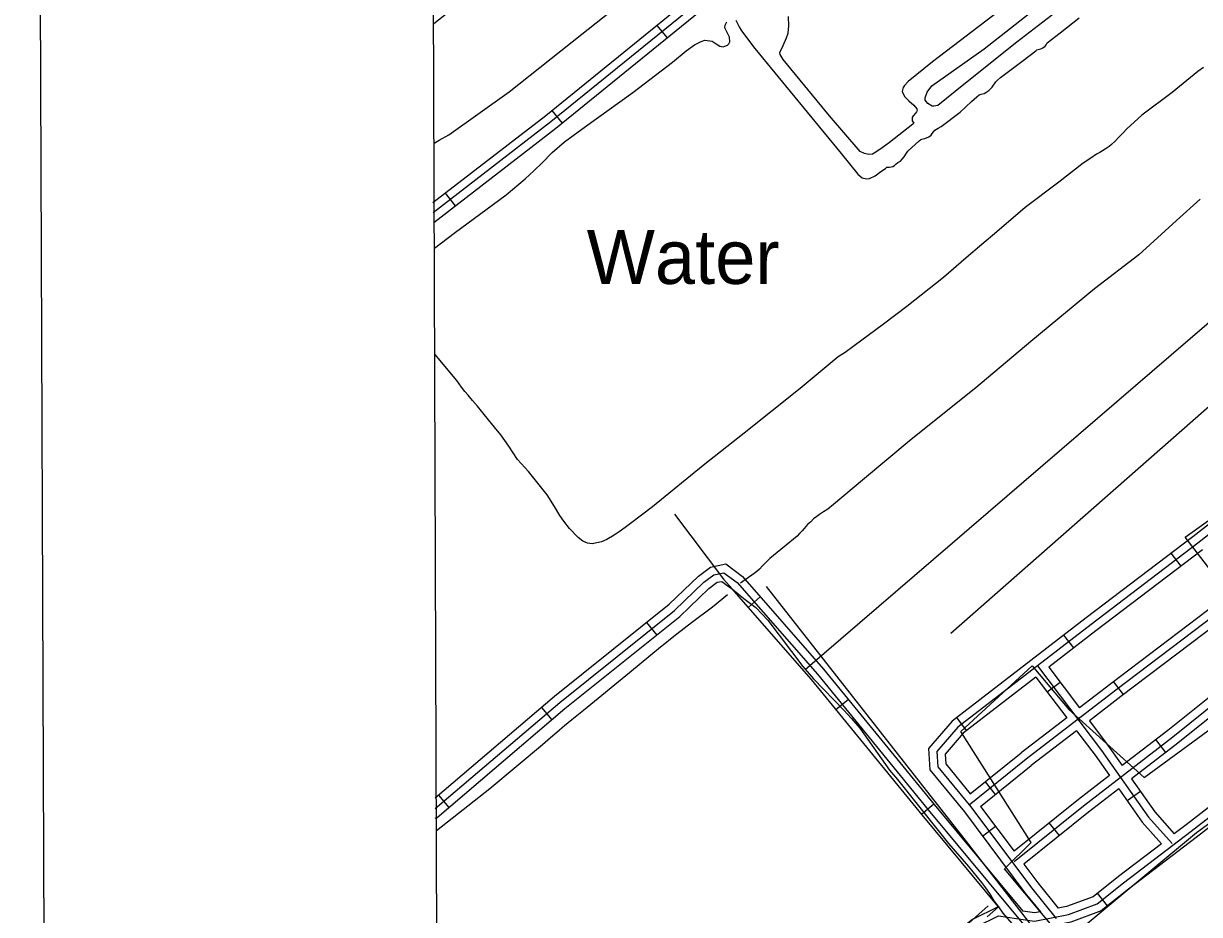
# Model space of a CAD drawing. Extents: x 3405885 to 3443815, y 558517 to 583997.
# Drawn here: x 3409221 to 3411396, y 573242 to 574891 of the extents above; entities that cross this region are included whole.
import ezdxf

# ---------------------------------------------------------------- set-up
doc = ezdxf.new("R2010")
doc.units = 0
for name, color, linetype in [('V-ANNO-SYMB', 7, 'Continuous'), ('V-DTCH-CNTR', 7, 'Continuous'), ('V-GRID-FRAM', 7, 'Continuous'), ('V-RIVR-IDEN', 7, 'Continuous'), ('V-ROAD-CNTR', 7, 'Continuous'), ('V-SITE-OTLN', 7, 'Continuous'), ('V-TOPO-SHOR', 7, 'Continuous')]:
    doc.layers.add(name, color=color, linetype=linetype)

msp = doc.modelspace()

# ---------------------------------------------------------------- linework, layer by layer
at = {"layer": 'V-ANNO-SYMB'}
msp.add_lwpolyline([(3409312.5, 559736.2), (3442395.5, 559868.5), (3442303.8, 582784.9), (3409220.9, 582652.6), (3409312.5, 559736.2)], dxfattribs=at)
at = {"layer": 'V-DTCH-CNTR'}
for points in [[(3410425.3, 573983.1), (3410515.7, 573863.2), (3410532.6, 573844.5), (3410553.2, 573826.9), (3410575.4, 573810.6), (3410587.5, 573798.3), (3410598, 573787.3), (3410662.3, 573701.5), (3410682.2, 573678.5), (3410738.4, 573620.8), (3410752.5, 573604.8), (3410768.1, 573587.5), (3410823, 573509.4), (3410837.5, 573492.5), (3410912.6, 573398), (3410931.8, 573373.5), (3410968.9, 573331), (3410977.1, 573321.4), (3410985, 573311.6), (3410992.8, 573301.6), (3411000.3, 573291.5), (3411007.7, 573281.3), (3411016, 573267.8), (3411024.2, 573256.4), (3411032.4, 573244.8), (3411111.8, 573153.4)], [(3411003.8, 573238), (3411024.2, 573256.4)]]:
    msp.add_lwpolyline(points, dxfattribs=at)
at = {"layer": 'V-GRID-FRAM'}
msp.add_lwpolyline([(3409954, 582088.9), (3441575.2, 582215.4), (3441655.9, 564032.2), (3410018.8, 563905.7), (3409954, 582088.9)], dxfattribs=at)
at = {"layer": 'V-ROAD-CNTR'}
for p, q in [((3410392.6, 574887.7), (3410411.5, 574864.4)), ((3410198.4, 574730.2), (3410217.3, 574706.9)), ((3410001, 574577.4), (3410019.4, 574553.6)), ((3411362.4, 573887.2), (3411344.2, 573911)), ((3410583.7, 573830.3), (3410561.2, 573810.5)), ((3410373.6, 573782.9), (3410392.3, 573759.5)), ((3411163.7, 573735.6), (3411145.4, 573759.4)), ((3411138.7, 573672), (3411114.7, 573653.9)), ((3411255.6, 573649.3), (3411237.5, 573673.3)), ((3410178.8, 573625.6), (3410198.2, 573602.7)), ((3410746.9, 573640.2), (3410723.6, 573621.2)), ((3410965.6, 573583), (3410947.3, 573606.8)), ((3411334, 573542.2), (3411315.7, 573566)), ((3410999.8, 573487.9), (3411018.6, 573464.5)), ((3409988.4, 573463.5), (3410007.9, 573440.6)), ((3411287.1, 573470.2), (3411262.6, 573453)), ((3410905.1, 573446.6), (3410881.8, 573427.7)), ((3411137.2, 573388.5), (3411118.5, 573411.9)), ((3411019.2, 573405), (3410995.1, 573387)), ((3411226.1, 573258.2), (3411207.5, 573281.8))]:
    msp.add_line(p, q, dxfattribs=at)
for points in [[(3409978.3, 574559.8), (3410186.8, 574720.9), (3410442.9, 574928.5)], [(3410468.6, 574930.1), (3410196.2, 574709.1), (3409978.4, 574540.9)], [(3409979.8, 574523.1), (3410205.5, 574697.3), (3410471, 574912.7)], [(3412013, 574429.4), (3412000.8, 574413), (3411589.4, 574101.5), (3411383.8, 573941.2)], [(3412025.1, 574420.5), (3412011.6, 574402.3), (3411598.5, 574089.6), (3411393.1, 573929.4)], [(3411384, 573941.3), (3411186.6, 573791.1), (3410938.6, 573600.1), (3410895.3, 573549.5), (3410897.4, 573509.9), (3410961.4, 573432.1), (3411073.5, 573282.6), (3411101.9, 573247.4)], [(3411393.1, 573929.4), (3411195.7, 573779.2), (3410949, 573589.2), (3410910.6, 573544.3), (3410912.1, 573515.6), (3410973.2, 573441.4), (3411085.3, 573291.8), (3411131.4, 573234.8)], [(3411402.1, 573917.5), (3411204.8, 573767.3), (3411117.5, 573700)], [(3409982.2, 573458.2), (3410203.3, 573646.4), (3410415.5, 573816.5), (3410469.4, 573868.7), (3410491.9, 573885.3), (3410520.2, 573891), (3410551.1, 573867.6), (3410700.8, 573696.6), (3410905.7, 573445.9), (3411069.8, 573248.4)], [(3409982.3, 573438.6), (3410212.8, 573634.9), (3410425.4, 573805.2), (3410479.1, 573857.2), (3410498.1, 573871.2), (3410516.6, 573874.9), (3410540.8, 573856.6), (3410689.4, 573686.9), (3410894.1, 573436.3), (3411116.8, 573168.4)], [(3409982.4, 573420.4), (3409985.9, 573421.9), (3410222.4, 573623.3), (3410435.3, 573794), (3410488.8, 573845.7), (3410504.3, 573857.2), (3410512.9, 573858.9), (3410530.5, 573845.5), (3410677.9, 573677.2), (3410882.5, 573426.8), (3411024.1, 573256.4)], [(3411465.1, 573845.4), (3411232.5, 573669.5), (3411174.5, 573624.7)], [(3411485.8, 573842.3), (3411241.6, 573657.5), (3411075.8, 573529.8)], [(3411483.3, 573821.6), (3411250.7, 573645.6), (3411192.6, 573600.8)], [(3411053.7, 573340.6), (3411181.7, 573443.4), (3411347.1, 573571.3), (3411498.3, 573692.4), (3411557.9, 573742.9)], [(3411542.2, 573749.2), (3411488.8, 573704), (3411337.8, 573583.1), (3411253.5, 573517.9)], [(3411576.9, 573739.3), (3411507.8, 573680.8), (3411356.3, 573559.5), (3411270.8, 573493.4)], [(3411096.5, 573702.8), (3411215.3, 573546), (3411302.2, 573422.8), (3411345.5, 573373.6)], [(3411117.5, 573700), (3411174.5, 573624.7)], [(3411093.7, 573681.7), (3410959.4, 573578.2), (3410925.9, 573539.1), (3410926.8, 573521.3), (3410972.4, 573465.9)], [(3411093.7, 573681.7), (3411150.7, 573606.4)], [(3410712.3, 573067), (3410745.4, 573045.9), (3410767.6, 573040.2), (3410809.9, 573068.1), (3410868.9, 573123.7), (3410940.3, 573185.1), (3410984.5, 573220.5), (3411024.5, 573239.9), (3411091.4, 573230.1), (3411154.3, 573242.6), (3411206.8, 573262.1), (3411255.8, 573300.8), (3411380.7, 573396.4), (3411489.4, 573480.6), (3411609.1, 573574.1), (3411652.4, 573605.7)], [(3411150.7, 573606.4), (3411066.7, 573541.7)], [(3411643.6, 573617.8), (3411600, 573586.1), (3411480.2, 573492.4), (3411371.6, 573408.3), (3411349.7, 573391.6)], [(3411168.8, 573582.5), (3411085, 573517.9)], [(3411661.2, 573593.6), (3411618.1, 573562.2), (3411498.6, 573468.7), (3411389.9, 573384.6), (3411265, 573289), (3411214.2, 573248.9), (3411158.4, 573228.1), (3411096.8, 573215.8)], [(3411168.8, 573582.5), (3411203.2, 573537.1), (3411229.7, 573499.5)], [(3411192.6, 573600.8), (3411227.4, 573554.8), (3411253.5, 573517.9)], [(3410972.4, 573465.9), (3411066.4, 573541.5)], [(3411075.8, 573529.8), (3410970.3, 573444.9)], [(3410991.1, 573442.4), (3411085.2, 573518.1)], [(3411229.7, 573499.5), (3411172.4, 573455.2), (3411053.3, 573359.5)], [(3411247, 573475), (3411190.9, 573431.6), (3411071.3, 573335.5)], [(3411247, 573475), (3411290.4, 573413.5), (3411325.8, 573373.3)], [(3411270.8, 573493.4), (3411314, 573432.1), (3411349.7, 573391.6)], [(3410991.1, 573442.4), (3411053.3, 573359.5)], [(3411325.8, 573373.3), (3411246.6, 573312.7), (3411199.4, 573275.4), (3411150.2, 573257.1), (3411135.1, 573254.1)], [(3411071.3, 573335.5), (3411097.1, 573301), (3411135.1, 573254.1)], [(3411024.1, 573256.4), (3410976.4, 573233.2), (3410930.7, 573196.7), (3410858.8, 573134.9), (3410800.5, 573079.9), (3410764.9, 573056.4), (3410751.4, 573059.9), (3410720.3, 573079.6)], [(3411101.9, 573247.4), (3411091, 573245.3), (3411069.8, 573248.4)]]:
    msp.add_lwpolyline(points, dxfattribs=at)
at = {"layer": 'V-SITE-OTLN'}
for points in [[(3411433.8, 573857.3), (3411370, 573940.7), (3411683.2, 574164.4)], [(3411548.7, 573508.2), (3411390.5, 573393.4), (3411148.5, 573191.7), (3411035.9, 573326.7), (3411085.1, 573375.8), (3410954.8, 573581.3), (3411086.6, 573702.7)], [(3411086.6, 573702.7), (3411154.6, 573621.6), (3411294.1, 573496.2), (3411420.8, 573589)]]:
    msp.add_lwpolyline(points, dxfattribs=at)
at = {"layer": 'V-TOPO-SHOR'}
for p, q in [((3410936.5, 573762.7), (3411671.8, 574409.9)), ((3410666.9, 573695.6), (3411490.1, 574403.7))]:
    msp.add_line(p, q, dxfattribs=at)
for points in [[(3411138.4, 574918), (3411058.4, 574856.6), (3410960.6, 574778.2), (3410912, 574739.6), (3410904.9, 574737.9), (3410902, 574737.9), (3410893.8, 574743.3), (3410889.1, 574749.2), (3410889.1, 574753.3), (3410892.7, 574763.9), (3410901.1, 574775.7), (3410998.2, 574844), (3411112.6, 574934), (3411224, 575020.6), (3411283.2, 575065.6), (3411288.6, 575066.7), (3411295.6, 575065.5), (3411303.9, 575069.6), (3411319.9, 575082.4), (3411378.6, 575130.4), (3411457.4, 575198.3)], [(3410007.5, 574685.1), (3410119.5, 574764.7), (3410254, 574871.2), (3410341.8, 574941.6), (3410364.8, 574954.9), (3410364.3, 574963.1), (3410342.7, 574991.4), (3410305.5, 575039.8), (3410290.3, 575050.4), (3410275.1, 575060.5), (3410267, 575068.2), (3410258.8, 575075.3), (3410253, 575080), (3410247.1, 575082.4), (3410241.3, 575084.2), (3410232.5, 575084.2), (3410225.4, 575082.5), (3410205.4, 575068.6), (3410139.9, 575012.7), (3410032, 574931.3), (3409979.6, 574890.7)], [(3411027, 574915.1), (3410902.5, 574820.5), (3410857.5, 574783.6), (3410850.4, 574776.6), (3410848, 574772.5), (3410846.2, 574765.4), (3410850.8, 574755.9), (3410858.4, 574748.2), (3410867.8, 574739.9), (3410873.7, 574733.4), (3410874.2, 574730.4), (3410873, 574727.5), (3410870.7, 574725.2), (3410866.5, 574720.5), (3410864.7, 574716.9), (3410864.7, 574711), (3410867.6, 574706.9), (3410865.8, 574704.6)], [(3409981.1, 574475.4), (3410017.8, 574503.3), (3410113.9, 574574.2), (3410149.1, 574604), (3410164.8, 574618.4), (3410180.5, 574633.6), (3410198.8, 574652.4), (3410221.8, 574671.9), (3410260.5, 574700.5), (3410347.8, 574763.3), (3410421.4, 574819.7), (3410446.6, 574840.4), (3410462, 574851.4), (3410474.2, 574857.7), (3410481.2, 574860.1), (3410495.1, 574858.3), (3410502.5, 574853.3), (3410509.1, 574849.2), (3410514.9, 574847.7), (3410518.4, 574848.9), (3410523, 574851.3), (3410525.7, 574853.2), (3410527.2, 574857.1), (3410527.1, 574866), (3410524.7, 574871), (3410521.9, 574876), (3410520.8, 574877.9), (3410518, 574882.9), (3410518.7, 574888.3), (3410522.1, 574894.5)], [(3410538.7, 574897), (3410545, 574885.1), (3410548.9, 574877.8), (3410573.6, 574844.8), (3410639, 574765.6), (3410733.3, 574650.4), (3410764.2, 574612.5), (3410772, 574605.6), (3410780.5, 574603.8), (3410785.9, 574604.2), (3410796.6, 574609), (3410807, 574617.2), (3410815.4, 574623.1), (3410818.1, 574625.1), (3410823.1, 574625.1), (3410829.3, 574626.3), (3410832.3, 574628.3), (3410835, 574631.4), (3410838.5, 574633.8), (3410843.1, 574636.5), (3410846.1, 574640), (3410850.3, 574644.7), (3410854.1, 574651.3), (3410856.6, 574654.8), (3410877.7, 574674), (3410881, 574676.3), (3410882.8, 574677.1), (3410885.2, 574677.9), (3410888.3, 574678.5), (3410895.7, 574681.2), (3410899.9, 574684.8), (3410901.9, 574687.4), (3410904.5, 574690.6), (3410906.8, 574693.5), (3410912.7, 574697.7), (3410918.6, 574700.3), (3410953.8, 574727.1), (3410974.6, 574746.8), (3410984.6, 574755.7), (3410989, 574758.9), (3410992.6, 574760.5), (3410998, 574761.8), (3411003.2, 574764.5), (3411006.8, 574767.3), (3411010.1, 574770.8), (3411012.7, 574773.6), (3411015.2, 574776.8), (3411017, 574779.4), (3411019.6, 574783), (3411022.4, 574786.2), (3411028.5, 574791.4), (3411070.2, 574822.4), (3411093.8, 574840.8), (3411095.6, 574842.2), (3411097.9, 574843), (3411102.6, 574844), (3411106.7, 574845.9), (3411110.8, 574849.1), (3411112.4, 574851.9), (3411114.7, 574855.1), (3411138.3, 574873.7), (3411173.8, 574901.6)], [(3410865.8, 574704.6), (3410823.1, 574671.2), (3410809.5, 574661.3), (3410797.7, 574653.1), (3410791.7, 574649.6), (3410784.7, 574648.5), (3410776.4, 574650.3), (3410768.8, 574654.5), (3410712, 574720.3), (3410626, 574824.6), (3410620.8, 574833.5), (3410620.2, 574837.6), (3410626.2, 574850.6), (3410632.2, 574864.7), (3410635.2, 574873.5), (3410636.5, 574887.1), (3410636, 574904.2)], [(3411403.6, 574809.4), (3411393, 574802.6), (3411345.5, 574763.7), (3411289.7, 574721.2), (3411261.7, 574696.5), (3411254.6, 574687.9), (3411246.9, 574680.5), (3411240.2, 574673.7), (3411233.8, 574667.4), (3411229.4, 574663.8), (3411222, 574658.5), (3411211.9, 574652.7), (3411205.7, 574649.3), (3411195.2, 574641.9), (3411181.3, 574632.4), (3411136.3, 574597.5), (3411073.9, 574550.7), (3411021.5, 574505.5), (3410993.8, 574482.2), (3410964.7, 574457.8), (3410922.6, 574421), (3410854.8, 574367.2), (3410811.9, 574334.6), (3410757.4, 574294.4), (3410740.7, 574282.3), (3410727.8, 574274.1), (3410657.4, 574215.8), (3410553.9, 574132.8), (3410478.4, 574073.2), (3410384.6, 573997), (3410343.5, 573965.7), (3410334, 573958.4), (3410322.6, 573950.2), (3410313.6, 573944.4), (3410300, 573936.5), (3410290.2, 573932), (3410272.6, 573928.2), (3410264, 573929.6), (3410255.7, 573933.2), (3410246.8, 573940.1), (3410230.8, 573956.7), (3410220.3, 573970.1), (3410212.7, 573980.9), (3410202.9, 573997.1), (3410189.5, 574019), (3410155.3, 574061.9), (3410134.9, 574084.5), (3410118.6, 574109.2), (3410103.8, 574130.3), (3410092.3, 574144.2), (3410081.2, 574157.5), (3410070.5, 574170.6), (3410060.5, 574182.9), (3410051.3, 574193.7), (3410043.2, 574203.2), (3410037.4, 574210.4), (3410030.8, 574218.4), (3410022.7, 574230.5), (3409981.8, 574279.5)], [(3409980.4, 574670), (3409989.5, 574675.1), (3410007.5, 574685.1)], [(3411397.5, 574566.2), (3411353.8, 574526.7), (3411284.1, 574463.2), (3411201.9, 574400), (3411084.2, 574302.4), (3410982.5, 574216.9), (3410863.2, 574121.2), (3410773, 574046.3), (3410719, 574001.2), (3410708.6, 573992.6), (3410700.9, 573987.5), (3410693.6, 573982.7), (3410688.2, 573978.8), (3410682.5, 573974.5), (3410677.1, 573969), (3410671.4, 573963.9), (3410664.9, 573956.5), (3410661, 573952.6), (3410656.5, 573947.5), (3410651.9, 573942.4), (3410601.6, 573900.9), (3410587.1, 573886.8), (3410582.1, 573881.7), (3410577.5, 573877), (3410572.5, 573873.1), (3410547.1, 573855.4)], [(3410594.7, 573849.5), (3410960.1, 573382.8), (3411203.6, 573069.9), (3411544, 573319.1)], [(3410523.4, 573834.2), (3410495.4, 573811.1), (3410456.6, 573782), (3410429.7, 573761.2), (3410417.8, 573751.8), (3410407.1, 573743.2), (3410399, 573736.9), (3410341.9, 573689.5), (3410256.7, 573619.7), (3410235.2, 573602.4), (3410221.4, 573591.4), (3410207.6, 573579.3), (3410195.7, 573569.5), (3410181.1, 573556.1), (3410083.3, 573475), (3409985, 573397.1)], [(3411005.6, 573258.2), (3410901.3, 573165.6), (3410812.3, 573086.4), (3410775.2, 573055.1), (3410769.1, 573050), (3410759.5, 573048), (3410751.7, 573048.3), (3410744, 573054.4), (3410649.9, 573157.5), (3410623.3, 573185.4), (3410613.2, 573191.9), (3410606.7, 573194.5), (3410599.7, 573194), (3410592.4, 573190.9), (3410495, 573103), (3410396, 573015.6)]]:
    msp.add_lwpolyline(points, dxfattribs=at)

# ---------------------------------------------------------------- texts
at = {"layer": 'V-RIVR-IDEN'}
msp.add_text('Water', height=100, dxfattribs=at).set_placement((3410262.7, 574409.2))

doc.saveas('drawing.dxf')
